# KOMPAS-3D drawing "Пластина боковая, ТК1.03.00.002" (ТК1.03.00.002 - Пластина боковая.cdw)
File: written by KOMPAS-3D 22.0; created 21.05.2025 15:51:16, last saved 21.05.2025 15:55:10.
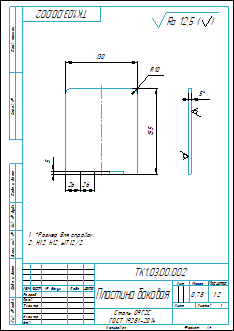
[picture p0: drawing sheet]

Sheet 1: A4, portrait

Document properties: Автор: TC; Знак неуказанной шероховатости: 4; Параметр неуказанной шероховатости: Ra 12,5; Масса: 0.778998; Полное имя файла: Пластина боковая.m3d

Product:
- Part/product: Пластина боковая  | designation ТК1.03.00.002
    Материал: Сталь 09Г2С ГОСТ 19281-2014 (density 7850 kg/m3)
    Масса: 0.778998
    Форматы листов документа: A4

Title block, sheet 1: Наименование: Пластина боковая; designation: ТК1.03.00.002; Материал: Сталь 09Г2С / ГОСТ 19281-2014; Масса: 0,78; Количество листов документа: 1; Форматы листов документа: A4; stored path: D:\Рабочая папка\АРХИВ\612\05\Задание №6 - Тележка для крыши\3Д\Узел монтажный\Пластина боковая.cdw

Views: Вид 1, Спереди, Проекционный вид 2
Referenced files in D:\Рабочая папка\АРХИВ\612\05\Задание №6 - Тележка для крыши\3Д\Узел монтажный\: Пластина боковая.m3d
Referenced files in D:\Работа\2025\5. Май\Задание №6 - Тележка для крыши\3Д\Узел монтажный\: Пластина боковая.m3d
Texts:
  Ra 12,5
  Ra 12,5 ( )
  BOSimple***Material:4ccf0190-16b6-4223-9222-aa108d28a442
  ТК1.03.00.002 Пластина боковая
Dimensions and other numbers on the sheet: 130; 155; 5; 26; 10; 1:2; 1; 0,78

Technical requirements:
  *Размер для справок.
  H12, h12, ±IT12/2.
